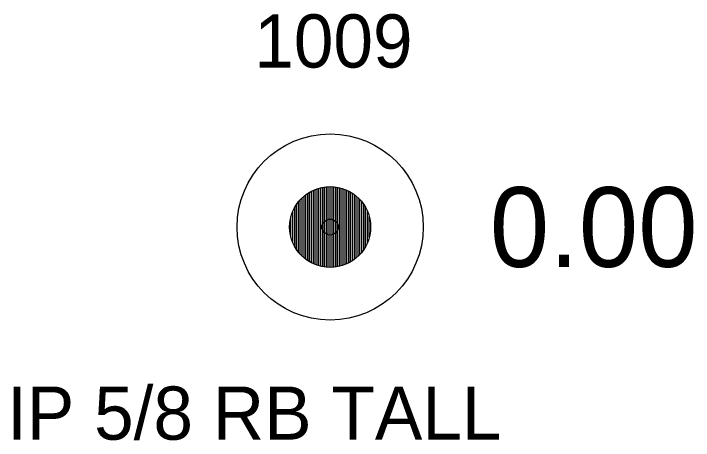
# Model space of a CAD drawing. Extents: x 1529475 to 1532053, y 876698 to 877911.
# Drawn here: x 1531828.73 to 1531841.5, y 877267.81 to 877275.83 of the extents above; entities that cross this region are included whole.
import ezdxf

# ---------------------------------------------------------------- set-up
doc = ezdxf.new("R2010")
doc.units = 0
for name, color, linetype in [('RD_EX_DV_Prop_txCode', 7, 'Continuous'), ('RD_EX_DV_PropPin', 7, 'Continuous'), ('RD_EX_TX_DV_Prop_ELEV', 7, 'Continuous'), ('RD_SMD_Locator', 7, 'Continuous')]:
    doc.layers.add(name, color=color, linetype=linetype)

msp = doc.modelspace()

# ---------------------------------------------------------------- linework, layer by layer
at = {"layer": 'RD_EX_DV_PropPin'}
for p, q in [((1531834.29, 877271.163), (1531834.29, 877272.476)), ((1531834.325, 877271.144), (1531834.325, 877272.495)), ((1531834.36, 877271.126), (1531834.36, 877272.512)), ((1531834.395, 877271.112), (1531834.395, 877272.527)), ((1531834.43, 877271.099), (1531834.43, 877272.54)), ((1531834.465, 877271.088), (1531834.465, 877272.551)), ((1531834.501, 877271.079), (1531834.501, 877272.56)), ((1531834.536, 877271.071), (1531834.536, 877272.567)), ((1531834.571, 877271.065), (1531834.571, 877272.573)), ((1531834.606, 877271.061), (1531834.606, 877272.577)), ((1531834.641, 877271.059), (1531834.641, 877272.579)), ((1531834.676, 877271.058), (1531834.676, 877272.58)), ((1531834.711, 877271.059), (1531834.711, 877272.579)), ((1531834.746, 877271.061), (1531834.746, 877272.577)), ((1531834.781, 877271.065), (1531834.781, 877272.573)), ((1531834.816, 877271.071), (1531834.816, 877272.567)), ((1531834.851, 877271.079), (1531834.851, 877272.56)), ((1531834.886, 877271.088), (1531834.886, 877272.551)), ((1531834.921, 877271.099), (1531834.921, 877272.54)), ((1531834.956, 877271.112), (1531834.956, 877272.527)), ((1531834.991, 877271.126), (1531834.991, 877272.512)), ((1531835.026, 877271.144), (1531835.026, 877272.495)), ((1531835.061, 877271.163), (1531835.061, 877272.476)), ((1531834.115, 877271.304), (1531834.115, 877272.334)), ((1531834.15, 877271.268), (1531834.15, 877272.37)), ((1531834.185, 877271.237), (1531834.185, 877272.401)), ((1531834.22, 877271.209), (1531834.22, 877272.429)), ((1531834.255, 877271.185), (1531834.255, 877272.454)), ((1531835.096, 877271.185), (1531835.096, 877272.454)), ((1531835.131, 877271.209), (1531835.131, 877272.429)), ((1531835.166, 877271.237), (1531835.166, 877272.401)), ((1531835.201, 877271.268), (1531835.201, 877272.37)), ((1531835.236, 877271.304), (1531835.236, 877272.334)), ((1531834.045, 877271.393), (1531834.045, 877272.246)), ((1531834.08, 877271.345), (1531834.08, 877272.293)), ((1531835.271, 877271.345), (1531835.271, 877272.293)), ((1531835.306, 877271.393), (1531835.306, 877272.246)), ((1531833.975, 877271.521), (1531833.975, 877272.117)), ((1531834.01, 877271.45), (1531834.01, 877272.189)), ((1531835.341, 877271.45), (1531835.341, 877272.189)), ((1531835.376, 877271.521), (1531835.376, 877272.117)), ((1531833.94, 877271.623), (1531833.94, 877272.015)), ((1531835.411, 877271.623), (1531835.411, 877272.015))]:
    msp.add_line(p, q, dxfattribs=at)
for radius in [1.75, 0.761]:
    msp.add_circle((1531834.676, 877271.819), radius, dxfattribs=at)
at = {"layer": 'RD_SMD_Locator'}
msp.add_circle((1531834.676, 877271.819), 0.15, dxfattribs=at)

# ---------------------------------------------------------------- texts
at = {"layer": 'RD_EX_DV_Prop_txCode'}
for s, p in [('1009', (1531833.25, 877274.819)), ('IP 5/8 RB TALL', (1531828.605, 877267.819))]:
    msp.add_text(s, height=1, dxfattribs=at).set_placement(p)
at = {"layer": 'RD_EX_TX_DV_Prop_ELEV'}
msp.add_text('0.00', height=1.5, dxfattribs=at).set_placement((1531837.676, 877271.069))

doc.saveas('drawing.dxf')
